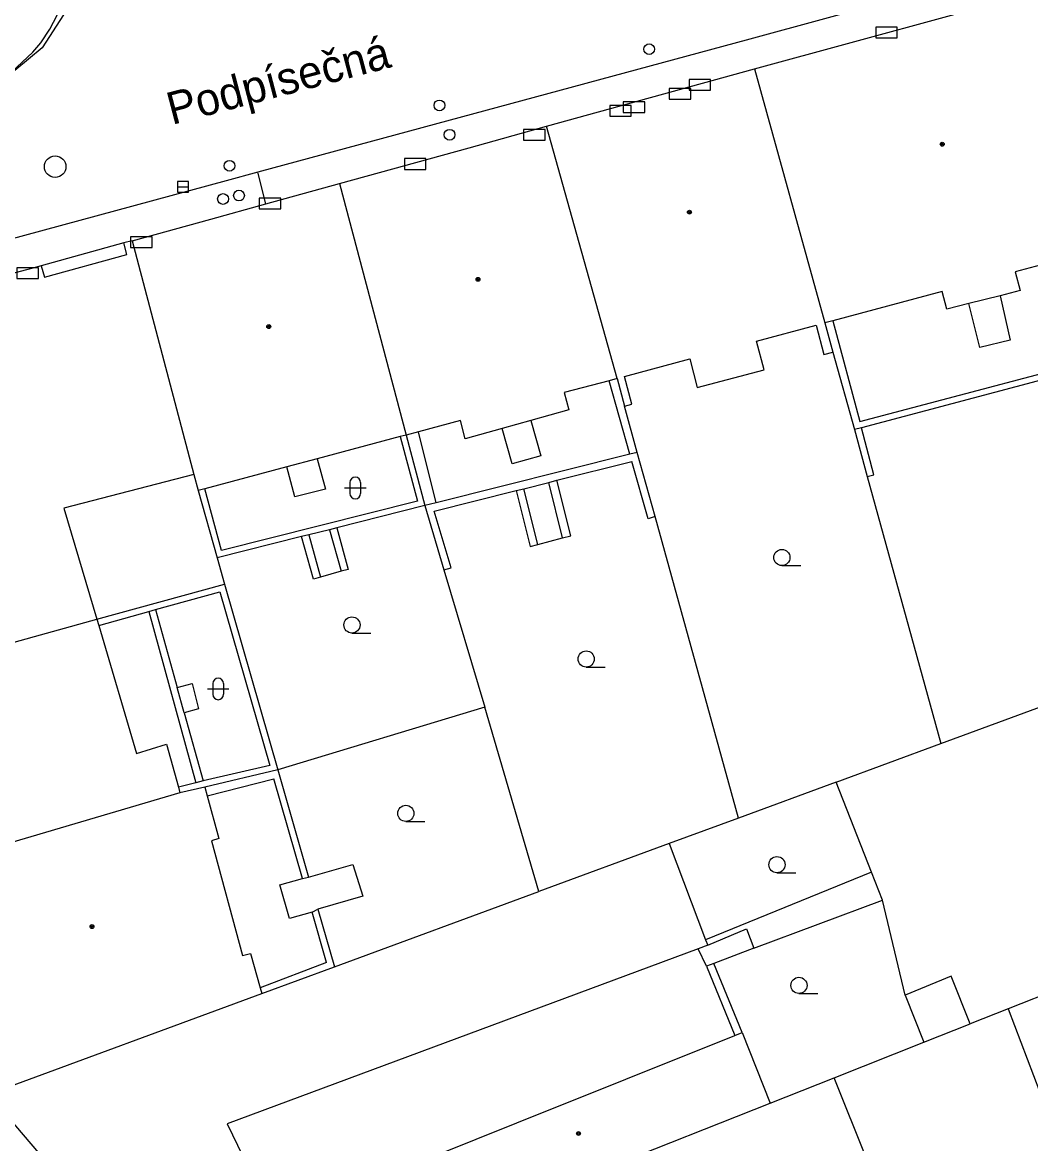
# Model space of a CAD drawing. Extents: x -595546 to -593986, y -1160845 to -1159202.
# Drawn here: x -595349 to -595302.2, y -1160752.4 to -1160700.3 of the extents above; entities that cross this region are included whole.
import ezdxf

# ---------------------------------------------------------------- set-up
doc = ezdxf.new("R2010")
doc.units = 0
for name, color, linetype in [('DOP - kresba z DSPS bez souradnic', 7, 'Continuous'), ('DOP - rozhrani ploch obecne', 7, 'Continuous'), ('Level 24', 7, 'Continuous'), ('Level 26', 7, 'Continuous'), ('Level 27', 7, 'Continuous'), ('Level 28', 7, 'Continuous'), ('Level 36', 7, 'Continuous'), ('Level 39', 7, 'Continuous'), ('Nazvy ulic', 7, 'Continuous'), ('Specificka linie pasportu komunikaci', 7, 'Continuous'), ('TM - budovy zdene_ betonove - VP', 7, 'Continuous'), ('TM - komunikace - VP', 7, 'Continuous'), ('TM - letecke snimky - pomocna linie', 7, 'Continuous'), ('TM - rozhrani ploch obecne - VP', 7, 'Continuous')]:
    doc.layers.add(name, color=color, linetype=linetype)

msp = doc.modelspace()

# ---------------------------------------------------------------- linework, layer by layer
at = {"layer": 'DOP - kresba z DSPS bez souradnic'}
for points in [[(-595304.54, -1160715.43), (-595305.05, -1160713.39)], [(-595303.6, -1160713.03), (-595303.13, -1160715.09)], [(-595311.35, -1160714.19), (-595310.11, -1160718.86)], [(-595310.11, -1160718.86), (-595296.76, -1160715.34)], [(-595303.13, -1160715.09), (-595304.54, -1160715.43)], [(-595320.77, -1160720.38), (-595321.73, -1160716.97)], [(-595326.24, -1160720.83), (-595326.7, -1160719.18)], [(-595325.37, -1160718.81), (-595324.91, -1160720.45)], [(-595309.45, -1160721.34), (-595310.03, -1160719.15)], [(-595331.43, -1160719.56), (-595330.63, -1160722.55)], [(-595329.76, -1160722.63), (-595330.58, -1160719.34)], [(-595335.28, -1160720.59), (-595334.9, -1160722)], [(-595324.91, -1160720.45), (-595326.24, -1160720.83)], [(-595324.16, -1160721.59), (-595320.68, -1160720.72)], [(-595319.93, -1160723.37), (-595320.68, -1160720.72)], [(-595336.32, -1160722.35), (-595336.69, -1160720.97)], [(-595325.7, -1160721.98), (-595324.54, -1160721.69)], [(-595324.54, -1160721.69), (-595324.16, -1160721.59)], [(-595323.9, -1160724.26), (-595324.54, -1160721.69)], [(-595323.52, -1160724.16), (-595324.16, -1160721.59)], [(-595309.76, -1160721.42), (-595309.45, -1160721.34)], [(-595339.72, -1160724.85), (-595340.5, -1160721.99)], [(-595334.9, -1160722), (-595336.32, -1160722.35)], [(-595329.86, -1160723.02), (-595326.05, -1160722.06)], [(-595326.05, -1160722.06), (-595325.7, -1160721.98)], [(-595326.05, -1160722.06), (-595325.4, -1160724.66)], [(-595325.05, -1160724.57), (-595325.7, -1160721.98)], [(-595330.63, -1160722.55), (-595339.72, -1160724.85)], [(-595329.06, -1160725.65), (-595329.86, -1160723.02)], [(-595319.6, -1160723.27), (-595319.93, -1160723.37)], [(-595334.71, -1160723.88), (-595334.17, -1160725.81)], [(-595334.37, -1160723.79), (-595333.84, -1160725.72)], [(-595335.46, -1160726.17), (-595336.01, -1160724.2)], [(-595335.67, -1160724.12), (-595335.13, -1160726.08)], [(-595325.05, -1160724.57), (-595323.9, -1160724.26)], [(-595323.9, -1160724.26), (-595323.52, -1160724.16)], [(-595325.4, -1160724.66), (-595325.05, -1160724.57)], [(-595334.17, -1160725.81), (-595335.13, -1160726.08)], [(-595333.84, -1160725.72), (-595334.17, -1160725.81)], [(-595329.4, -1160725.75), (-595329.06, -1160725.65)], [(-595335.13, -1160726.08), (-595335.46, -1160726.17)], [(-595342.78, -1160727.59), (-595339.8, -1160726.77)], [(-595339.8, -1160726.77), (-595337.48, -1160734.82)], [(-595345.42, -1160728.32), (-595343.09, -1160727.68)], [(-595343.09, -1160727.68), (-595342.78, -1160727.59)], [(-595343.09, -1160727.68), (-595340.92, -1160735.62)], [(-595342.78, -1160727.59), (-595341.78, -1160731.2)], [(-595341.78, -1160731.2), (-595341.08, -1160731.01)], [(-595341.08, -1160731.01), (-595340.79, -1160732.19)], [(-595341.45, -1160732.37), (-595341.78, -1160731.2)], [(-595340.79, -1160732.19), (-595341.45, -1160732.37)], [(-595341.45, -1160732.37), (-595340.58, -1160735.53)], [(-595337.48, -1160734.82), (-595340.58, -1160735.53)], [(-595337.11, -1160735.02), (-595335.68, -1160740)], [(-595340.92, -1160735.62), (-595341.72, -1160735.82)], [(-595340.58, -1160735.53), (-595340.92, -1160735.62)], [(-595340.39, -1160736.23), (-595337.3, -1160735.44)], [(-595335.97, -1160740.06), (-595337.3, -1160735.44)], [(-595335.68, -1160740), (-595333.63, -1160739.41)], [(-595333.63, -1160739.41), (-595333.16, -1160740.88)], [(-595309.56, -1160739.77), (-595317.26, -1160742.9)], [(-595337.02, -1160740.36), (-595335.97, -1160740.06)], [(-595336.57, -1160741.92), (-595337.02, -1160740.36)], [(-595333.16, -1160740.88), (-595335.25, -1160741.48)], [(-595315.02, -1160743.3), (-595309.06, -1160741.06)], [(-595335.25, -1160741.48), (-595334.48, -1160744.16)], [(-595335.52, -1160741.62), (-595336.57, -1160741.92)], [(-595334.85, -1160743.95), (-595335.52, -1160741.62)], [(-595317.16, -1160743.16), (-595315.36, -1160742.4)], [(-595315.36, -1160742.4), (-595315.02, -1160743.3)], [(-595317.22, -1160744.13), (-595317.6, -1160743.32)], [(-595315.02, -1160743.3), (-595316.88, -1160744)], [(-595334.85, -1160743.95), (-595337.93, -1160745.13)], [(-595316.88, -1160744), (-595317.22, -1160744.13)], [(-595317.22, -1160744.13), (-595315.91, -1160747.35)], [(-595315.56, -1160747.21), (-595316.88, -1160744)], [(-595308, -1160745.48), (-595307.14, -1160747.66)]]:
    msp.add_lwpolyline(points, dxfattribs=at)
at = {"layer": 'DOP - rozhrani ploch obecne'}
for points in [[(-595311.36, -1160715.64), (-595310.36, -1160719.24)], [(-595296.69, -1160715.62), (-595310.03, -1160719.15)], [(-595320.43, -1160720.3), (-595321.02, -1160718.15)], [(-595310.03, -1160719.15), (-595310.36, -1160719.24)], [(-595331.16, -1160719.49), (-595330.28, -1160722.76)], [(-595310.36, -1160719.24), (-595309.76, -1160721.42)], [(-595320.77, -1160720.38), (-595329.76, -1160722.63)], [(-595320.43, -1160720.3), (-595320.77, -1160720.38)], [(-595319.6, -1160723.27), (-595320.43, -1160720.3)], [(-595309.76, -1160721.42), (-595306.34, -1160733.8)], [(-595340.8, -1160722.07), (-595339.93, -1160725.19)], [(-595330.28, -1160722.76), (-595334.37, -1160723.79)], [(-595329.76, -1160722.63), (-595330.28, -1160722.76)], [(-595330.28, -1160722.76), (-595329.4, -1160725.75)], [(-595315.74, -1160737.26), (-595319.6, -1160723.27)], [(-595334.71, -1160723.88), (-595335.67, -1160724.12)], [(-595334.37, -1160723.79), (-595334.71, -1160723.88)], [(-595336.01, -1160724.2), (-595339.93, -1160725.19)], [(-595335.67, -1160724.12), (-595336.01, -1160724.2)], [(-595339.93, -1160725.19), (-595339.59, -1160726.4)], [(-595329.4, -1160725.75), (-595327.51, -1160732.12)], [(-595345.51, -1160728.03), (-595339.59, -1160726.4)], [(-595339.59, -1160726.4), (-595337.11, -1160735.02)], [(-595306.34, -1160733.8), (-595292.65, -1160728.76)], [(-595327.51, -1160732.12), (-595337.11, -1160735.02)], [(-595325, -1160740.67), (-595327.51, -1160732.12)], [(-595311.2, -1160735.59), (-595306.34, -1160733.8)], [(-595337.11, -1160735.02), (-595340.5, -1160735.82)], [(-595311.2, -1160735.59), (-595315.74, -1160737.26)], [(-595309.56, -1160739.77), (-595311.2, -1160735.59)], [(-595315.74, -1160737.26), (-595318.95, -1160738.44)], [(-595309.06, -1160741.06), (-595309.56, -1160739.77)], [(-595308, -1160745.48), (-595309.06, -1160741.06)], [(-595305.87, -1160744.59), (-595308, -1160745.48)], [(-595304.99, -1160746.81), (-595305.87, -1160744.59)]]:
    msp.add_lwpolyline(points, dxfattribs=at)
at = {"layer": 'Level 24'}
for points in [[(-595309.368, -1160701.069), (-595308.368, -1160701.069), (-595308.368, -1160700.569), (-595309.368, -1160700.569)], [(-595318.028, -1160703.499), (-595317.028, -1160703.499), (-595317.028, -1160702.999), (-595318.028, -1160702.999)], [(-595318.947, -1160703.908), (-595317.947, -1160703.908), (-595317.947, -1160703.408), (-595318.947, -1160703.408)], [(-595321.087, -1160704.528), (-595320.087, -1160704.528), (-595320.087, -1160704.028), (-595321.087, -1160704.028)], [(-595321.707, -1160704.698), (-595320.707, -1160704.698), (-595320.707, -1160704.198), (-595321.707, -1160704.198)], [(-595325.707, -1160705.818), (-595324.707, -1160705.818), (-595324.707, -1160705.318), (-595325.707, -1160705.318)], [(-595331.238, -1160707.169), (-595330.238, -1160707.169), (-595330.238, -1160706.669), (-595331.238, -1160706.669)], [(-595337.968, -1160708.999), (-595336.968, -1160708.999), (-595336.968, -1160708.499), (-595337.968, -1160708.499)], [(-595343.937, -1160710.798), (-595342.937, -1160710.798), (-595342.937, -1160710.298), (-595343.937, -1160710.298)], [(-595349.217, -1160712.228), (-595348.217, -1160712.228), (-595348.217, -1160711.728), (-595349.217, -1160711.728)]]:
    msp.add_lwpolyline(points, close=True, dxfattribs=at)
at = {"layer": 'Level 26'}
for centre in [(-595319.88, -1160701.59), (-595329.61, -1160704.2), (-595339.35, -1160707), (-595339.65, -1160708.54)]:
    msp.add_circle(centre, 0.25, dxfattribs=at)
at = {"layer": 'Level 27'}
msp.add_line((-595341.76, -1160707.98), (-595341.26, -1160707.98), dxfattribs=at)
msp.add_lwpolyline([(-595341.76, -1160708.23), (-595341.26, -1160708.23), (-595341.26, -1160707.73), (-595341.76, -1160707.73)], close=True, dxfattribs=at)
msp.add_circle((-595347.44, -1160707.04), 0.5, dxfattribs=at)
at = {"layer": 'Level 28'}
for centre in [(-595329.14, -1160705.56), (-595338.91, -1160708.38)]:
    msp.add_circle(centre, 0.25, dxfattribs=at)
at = {"layer": 'Level 36'}
for p, q in [((-595333.766, -1160721.696), (-595333.766, -1160722.196)), ((-595333.266, -1160721.696), (-595333.266, -1160722.196)), ((-595334.016, -1160721.946), (-595333.016, -1160721.946)), ((-595313.72, -1160725.545), (-595312.845, -1160725.545)), ((-595333.67, -1160728.675), (-595332.795, -1160728.675)), ((-595322.8, -1160730.255), (-595321.925, -1160730.255)), ((-595340.126, -1160731.016), (-595340.126, -1160731.516)), ((-595339.626, -1160731.016), (-595339.626, -1160731.516)), ((-595340.376, -1160731.266), (-595339.376, -1160731.266)), ((-595331.17, -1160737.415), (-595330.295, -1160737.415)), ((-595313.95, -1160739.795), (-595313.075, -1160739.795)), ((-595312.93, -1160745.395), (-595312.055, -1160745.395))]:
    msp.add_line(p, q, dxfattribs=at)
for centre in [(-595313.72, -1160725.17), (-595333.67, -1160728.3), (-595322.8, -1160729.88), (-595331.17, -1160737.04), (-595313.95, -1160739.42), (-595312.93, -1160745.02)]:
    msp.add_circle(centre, 0.375, dxfattribs=at)
for centre, start, end in [((-595333.516, -1160721.696), 0, 180), ((-595333.516, -1160722.196), 180, 0), ((-595339.876, -1160731.016), 0, 180), ((-595339.876, -1160731.516), 180, 0)]:
    msp.add_arc(centre, 0.25, start, end, dxfattribs=at)
at = {"layer": 'Level 39'}
for centre, radius in [((-595306.28, -1160706), 0.09), ((-595306.28, -1160706), 0.0398), ((-595318.01, -1160709.15), 0.09), ((-595318.01, -1160709.15), 0.0398), ((-595327.82, -1160712.27), 0.09), ((-595327.82, -1160712.27), 0.0398), ((-595337.53, -1160714.46), 0.09), ((-595337.53, -1160714.46), 0.0398), ((-595345.73, -1160742.29), 0.09), ((-595345.73, -1160742.29), 0.0398), ((-595323.16, -1160751.89), 0.09), ((-595323.16, -1160751.89), 0.0398)]:
    msp.add_circle(centre, radius, dxfattribs=at)
at = {"layer": 'Specificka linie pasportu komunikaci'}
for points in [[(-595349.95, -1160703.1), (-595348.48, -1160701.73), (-595348.11, -1160701.3), (-595347.69, -1160700.67), (-595347.34, -1160700.01), (-595347.06, -1160699.31), (-595346.85, -1160698.59), (-595346.73, -1160697.85), (-595346.69, -1160697.45)], [(-595337.66, -1160708.76), (-595338.02, -1160707.36), (-595338.03, -1160707.3)]]:
    msp.add_lwpolyline(points, dxfattribs=at)
at = {"layer": 'TM - budovy zdene_ betonove - VP'}
for points in [[(-595314.99, -1160702.51), (-595301.36, -1160698.77)], [(-595324.64, -1160705.17), (-595314.99, -1160702.51)], [(-595314.99, -1160702.51), (-595311.73, -1160714.29)], [(-595328.23, -1160706.16), (-595324.64, -1160705.17)], [(-595321.37, -1160716.87), (-595324.64, -1160705.17)], [(-595334.25, -1160707.82), (-595328.23, -1160706.16)], [(-595337.66, -1160708.76), (-595334.25, -1160707.82)], [(-595334.25, -1160707.82), (-595331.16, -1160719.49)], [(-595340.22, -1160709.47), (-595337.66, -1160708.76)], [(-595343.87, -1160710.48), (-595340.22, -1160709.47)], [(-595343.87, -1160710.48), (-595344.26, -1160710.58)], [(-595344.11, -1160711.11), (-595344.26, -1160710.58)], [(-595343.87, -1160710.48), (-595341.01, -1160721.32)], [(-595298.02, -1160710.62), (-595302.9, -1160711.92)], [(-595347.94, -1160712.17), (-595344.11, -1160711.11)], [(-595348.09, -1160711.64), (-595348.48, -1160711.75), (-595349.06, -1160711.91), (-595357.67, -1160714.26)], [(-595348.09, -1160711.64), (-595347.94, -1160712.17)], [(-595302.9, -1160711.92), (-595302.67, -1160712.79)], [(-595306.29, -1160712.83), (-595311.35, -1160714.19)], [(-595306.07, -1160713.65), (-595306.29, -1160712.83)], [(-595302.67, -1160712.79), (-595303.6, -1160713.03)], [(-595305.05, -1160713.39), (-595306.07, -1160713.65)], [(-595303.6, -1160713.03), (-595305.05, -1160713.39)], [(-595314.9, -1160715.14), (-595312.13, -1160714.4)], [(-595312.13, -1160714.4), (-595311.78, -1160715.75)], [(-595311.35, -1160714.19), (-595311.73, -1160714.29)], [(-595311.73, -1160714.29), (-595311.36, -1160715.64)], [(-595314.55, -1160716.47), (-595314.9, -1160715.14)], [(-595321.03, -1160716.78), (-595318, -1160715.96)], [(-595318, -1160715.96), (-595317.65, -1160717.28)], [(-595311.78, -1160715.75), (-595311.36, -1160715.64)], [(-595317.65, -1160717.28), (-595314.55, -1160716.47)], [(-595321.73, -1160716.97), (-595323.82, -1160717.52)], [(-595321.37, -1160716.87), (-595321.73, -1160716.97)], [(-595321.37, -1160716.87), (-595321.02, -1160718.15)], [(-595320.68, -1160718.06), (-595321.03, -1160716.78)], [(-595323.82, -1160717.52), (-595323.61, -1160718.32)], [(-595321.02, -1160718.15), (-595320.68, -1160718.06)], [(-595323.61, -1160718.32), (-595325.37, -1160718.81)], [(-595328.64, -1160718.81), (-595330.58, -1160719.34)], [(-595328.41, -1160719.66), (-595328.64, -1160718.81)], [(-595326.7, -1160719.18), (-595328.41, -1160719.66)], [(-595325.37, -1160718.81), (-595326.7, -1160719.18)], [(-595331.43, -1160719.56), (-595335.28, -1160720.59)], [(-595331.16, -1160719.49), (-595331.43, -1160719.56)], [(-595330.58, -1160719.34), (-595331.16, -1160719.49)], [(-595335.28, -1160720.59), (-595336.69, -1160720.97)], [(-595336.69, -1160720.97), (-595340.5, -1160721.99)], [(-595341.01, -1160721.32), (-595347.03, -1160722.88)], [(-595341.01, -1160721.32), (-595340.8, -1160722.07)], [(-595340.5, -1160721.99), (-595340.8, -1160722.07)], [(-595347.03, -1160722.88), (-595345.51, -1160728.03)], [(-595355.8, -1160730.89), (-595345.51, -1160728.03)], [(-595345.51, -1160728.03), (-595345.42, -1160728.32)], [(-595345.42, -1160728.32), (-595343.67, -1160734.26)], [(-595343.67, -1160734.26), (-595342.27, -1160733.83)], [(-595342.27, -1160733.83), (-595341.72, -1160735.82)], [(-595341.72, -1160735.82), (-595341.65, -1160736.09)], [(-595340.5, -1160735.82), (-595341.65, -1160736.09)], [(-595340.5, -1160735.82), (-595340.39, -1160736.23)], [(-595341.65, -1160736.09), (-595353.45, -1160739.56)], [(-595340.39, -1160736.23), (-595339.84, -1160738.21)], [(-595339.84, -1160738.21), (-595340.19, -1160738.31)], [(-595340.19, -1160738.31), (-595338.75, -1160743.64)], [(-595318.95, -1160738.44), (-595325, -1160740.67)], [(-595318.95, -1160738.44), (-595317.26, -1160742.9)], [(-595334.48, -1160744.16), (-595325, -1160740.67)], [(-595317.26, -1160742.9), (-595317.16, -1160743.16)], [(-595317.6, -1160743.32), (-595339.46, -1160751.44)], [(-595338.75, -1160743.64), (-595338.37, -1160743.54)], [(-595338.37, -1160743.54), (-595337.93, -1160745.13)], [(-595317.16, -1160743.16), (-595317.6, -1160743.32)], [(-595337.85, -1160745.4), (-595334.48, -1160744.16)], [(-595298.37, -1160744.19), (-595303.23, -1160746.11)], [(-595337.93, -1160745.13), (-595337.85, -1160745.4)], [(-595350.54, -1160750.07), (-595337.85, -1160745.4)], [(-595303.23, -1160746.11), (-595304.99, -1160746.81)], [(-595303.23, -1160746.11), (-595301.46, -1160750.75)], [(-595315.91, -1160747.35), (-595315.56, -1160747.21)], [(-595315.56, -1160747.21), (-595314.26, -1160750.49)], [(-595307.14, -1160747.66), (-595304.99, -1160746.81)], [(-595326.02, -1160751.4), (-595315.91, -1160747.35)], [(-595311.29, -1160749.31), (-595307.14, -1160747.66)], [(-595314.26, -1160750.49), (-595311.29, -1160749.31)], [(-595309.77, -1160753.13), (-595311.29, -1160749.31)], [(-595346.95, -1160754.25), (-595350.54, -1160750.07)], [(-595321.92, -1160753.52), (-595314.26, -1160750.49)], [(-595339.46, -1160751.44), (-595337.29, -1160755.91)], [(-595333.64, -1160754.45), (-595326.02, -1160751.4)]]:
    msp.add_lwpolyline(points, dxfattribs=at)
at = {"layer": 'TM - komunikace - VP'}
for points in [[(-595273.47, -1160689.74), (-595315.21, -1160701.12), (-595338.03, -1160707.3)], [(-595347.05, -1160700), (-595348.04, -1160701.53)], [(-595348.04, -1160701.53), (-595349.95, -1160703.1)], [(-595339.51, -1160707.7), (-595360.8, -1160713.47)], [(-595338.03, -1160707.3), (-595339.51, -1160707.7)]]:
    msp.add_lwpolyline(points, dxfattribs=at)
at = {"layer": 'TM - letecke snimky - pomocna linie'}
for points in [[(-595335.97, -1160740.06), (-595335.68, -1160740)], [(-595335.52, -1160741.62), (-595335.25, -1160741.48)]]:
    msp.add_lwpolyline(points, dxfattribs=at)
at = {"layer": 'TM - rozhrani ploch obecne - VP'}
msp.add_lwpolyline([(-595344.26, -1160710.58), (-595348.09, -1160711.64)], dxfattribs=at)

# ---------------------------------------------------------------- texts
at = {"layer": 'Nazvy ulic'}
msp.add_text('Podpísečná', height=1.5, rotation=14.749, dxfattribs=at).set_placement((-595342.024, -1160705.109))

doc.saveas('drawing.dxf')
